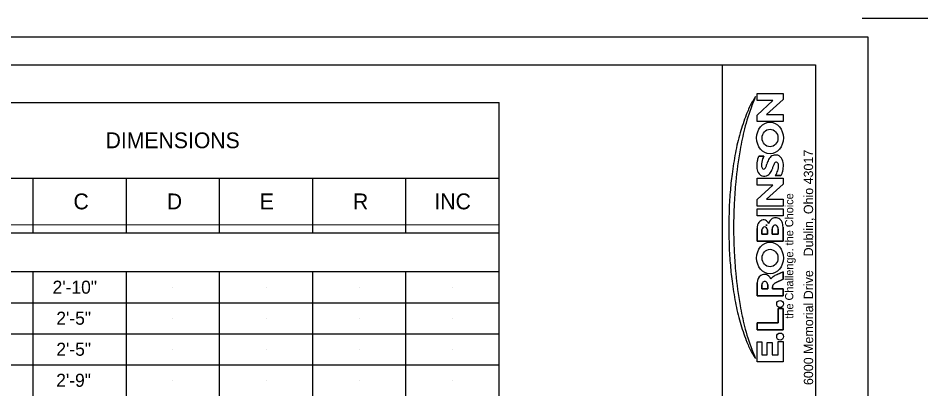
# Model space of a CAD drawing. Extents: x -9.2 to 26.7, y -0.9 to 21.1.
# Drawn here: x 16.98 to 26.74, y 17.13 to 21.11 of the extents above; entities that cross this region are included whole.
import ezdxf

# ---------------------------------------------------------------- set-up
doc = ezdxf.new("R2010")
doc.units = 0
for name, color, linetype in [('BR_P_Gen_Text', 7, 'Continuous'), ('Default', 7, 'Continuous'), ('SC_Scratch1', 7, 'Continuous'), ('SH_Border', 7, 'Continuous'), ('SH_Cut_Line', 7, 'Continuous'), ('SH_Data', 7, 'Continuous'), ('TX_P_1', 7, 'Continuous')]:
    doc.layers.add(name, color=color, linetype=linetype)

msp = doc.modelspace()

# ---------------------------------------------------------------- linework, layer by layer
at = {"layer": 'BR_P_Gen_Text'}
for p, q in [((7.6374, 20.2067), (22.1367, 20.2067)), ((22.1368, 11.7231), (22.1367, 20.2066)), ((15.1373, 19.394), (22.1368, 19.3941)), ((17.1372, 18.8063), (17.1372, 19.394)), ((18.1371, 18.8063), (18.1371, 19.394)), ((19.137, 18.8064), (19.137, 19.3941)), ((20.1369, 18.8064), (20.1369, 19.3941)), ((21.1368, 18.8064), (21.1369, 19.3941)), ((7.6374, 18.8942), (22.1367, 18.8943)), ((7.6374, 18.8066), (22.1367, 18.8066)), ((7.6374, 18.3898), (22.1367, 18.3899)), ((7.6374, 18.3898), (22.1367, 18.3899)), ((17.1372, 12.0564), (17.1372, 18.3896)), ((18.1372, 12.0564), (18.1371, 18.3896)), ((19.1371, 12.0564), (19.137, 18.3897)), ((20.137, 12.0564), (20.1369, 18.3898)), ((21.1369, 12.0564), (21.1368, 18.3898)), ((7.6374, 18.0565), (22.1367, 18.0565)), ((7.6374, 17.7232), (22.1367, 17.7232)), ((7.6374, 17.3899), (22.1367, 17.3899))]:
    msp.add_line(p, q, dxfattribs=at)
at = {"layer": 'Default'}
for p, q in [((25.163, 19.4213), (25.1012, 19.4213)), ((25.1012, 19.4213), (25.163, 19.4213)), ((24.9065, 18.7178), (24.9065, 18.8527)), ((25.1852, 18.8681), (25.1852, 18.7178)), ((24.9576, 18.8383), (24.9576, 18.7928)), ((24.9576, 18.7928), (24.9576, 18.8383)), ((25.1852, 18.7178), (24.9065, 18.7178)), ((25.1852, 18.3082), (25.1037, 18.2684)), ((25.1037, 18.2684), (25.1852, 18.3082)), ((24.9571, 18.2474), (24.9571, 18.2048)), ((24.9571, 18.2048), (24.9571, 18.2474)), ((24.9571, 18.2048), (25.0203, 18.2048)), ((25.0203, 18.2048), (24.9571, 18.2048)), ((25.0203, 18.2048), (25.0203, 18.2474)), ((25.0203, 18.2474), (25.0203, 18.2048))]:
    msp.add_line(p, q, dxfattribs=at)
for points in [[(25.1852, 20.0021), (24.9065, 20.0021), (24.9065, 20.0711), (25.075, 20.2269), (24.9065, 20.2269), (24.9065, 20.3013), (25.1852, 20.3013), (25.1852, 20.2372), (25.0077, 20.0759), (25.1852, 20.0759)], [(25.1852, 19.094), (24.9065, 19.094), (24.9065, 19.163), (25.075, 19.3189), (24.9065, 19.3189), (24.9065, 19.3933), (25.1852, 19.3933), (25.1852, 19.3291), (25.0077, 19.1679), (25.1852, 19.1679)], [(24.9065, 18.9898), (24.9065, 19.0638), (25.1852, 19.0638), (25.1852, 18.9898)], [(24.9065, 17.4223), (24.9065, 17.6368), (24.958, 17.6368), (24.958, 17.4973), (25.0152, 17.4973), (25.0152, 17.6293), (25.0667, 17.6293), (25.0667, 17.4973), (25.1337, 17.4973), (25.1337, 17.6399), (25.1852, 17.6399), (25.1852, 17.4223)]]:
    msp.add_lwpolyline(points, close=True, dxfattribs=at)
for points in [[(24.9244, 19.6286), (24.9797, 19.6286), (24.9686, 19.6018)], [(24.9686, 19.6018), (24.9797, 19.6286), (24.9244, 19.6286)], [(25.1852, 18.8681), (25.1852, 18.7178), (24.9065, 18.7178), (24.9065, 18.8527)], [(24.9065, 18.8527), (24.9065, 18.7178), (25.1852, 18.7178)], [(25.0678, 18.8473), (25.0678, 18.7928), (25.1333, 18.7928), (25.1333, 18.8473)], [(25.1333, 18.8473), (25.1333, 18.7928), (25.0678, 18.7928), (25.0678, 18.8473)], [(25.1852, 18.7178), (25.1852, 18.8681)], [(24.9576, 18.7928), (25.0167, 18.7928), (25.0167, 18.8383)], [(25.0167, 18.8383), (25.0167, 18.7928), (24.9576, 18.7928)], [(25.1204, 18.3578), (25.1852, 18.3894), (25.1852, 18.3082)], [(25.1852, 18.3082), (25.1852, 18.3894), (25.1204, 18.3578)], [(25.072, 18.2264), (25.072, 18.2048), (25.1852, 18.2048), (25.1852, 18.1298), (24.9065, 18.1298), (24.9065, 18.2048), (24.9065, 18.2691)], [(24.9065, 18.2691), (24.9065, 18.2048), (24.9065, 18.1298), (25.1852, 18.1298)], [(24.9571, 18.2474), (24.9571, 18.2048), (25.0203, 18.2048), (25.0203, 18.2474)], [(25.1852, 18.1298), (25.1852, 18.2048), (25.072, 18.2048), (25.072, 18.2264)], [(24.9065, 17.7659), (24.9065, 17.8409), (25.1337, 17.8409), (25.1337, 17.9928), (25.1852, 17.9928), (25.1852, 17.7659), (24.9065, 17.7659)], [(25.1852, 17.9928), (25.1337, 17.9928), (25.1337, 17.8409), (24.9065, 17.8409), (24.9065, 17.7659)], [(24.9065, 17.7659), (25.1852, 17.7659), (25.1852, 17.9928)]]:
    msp.add_lwpolyline(points, dxfattribs=at)
for centre, major_axis, ratio, start_param, end_param in [((25.6694, 19.5945), (0, 1.1412), 0.85, 0.988431, 1.105191), ((25.6694, 19.5945), (0, 1.1412), 0.85, 0.988431, 1.105191), ((-13.5953, 41.3688), (0, 49.9526), 0.85, 4.274094, 4.276309), ((-13.5953, 41.3688), (0, 49.9526), 0.85, 4.274094, 4.276309), ((25.1167, 20.0227), (0, 0.3626), 0.85, 0.822588, 0.988431), ((25.1167, 20.0227), (0, 0.3626), 0.85, 0.822588, 0.988431), ((26.1479, 19.454), (0, 1.6851), 0.85, 1.132502, 1.288747), ((26.1479, 19.454), (0, 1.6851), 0.85, 1.132502, 1.288747), ((27.2215, 18.8487), (0, 3.1123), 0.85, 1.165908, 1.233316), ((27.2215, 18.8487), (0, 3.1123), 0.85, 1.165908, 1.233316), ((25.2455, 19.845), (0, 0.5832), 0.85, 1.105191, 1.165908), ((25.2455, 19.845), (0, 0.5832), 0.85, 1.105191, 1.165908), ((27.6458, 18.9434), (0, 3.5199), 0.85, 1.288747, 1.354281), ((27.6458, 18.9434), (0, 3.5199), 0.85, 1.288747, 1.354281), ((26.4308, 19.1969), (0, 2.1194), 0.85, 1.243005, 1.347881), ((26.4308, 19.1969), (0, 2.1194), 0.85, 1.243005, 1.347881), ((25.0453, 19.8252), (0, -0.0938), 0.910305, 4.71238898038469, 4.712389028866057), ((27.6198, 18.9266), (0, 3.5437), 0.85, 1.360764, 1.426378), ((27.6198, 18.9266), (0, 3.5437), 0.85, 1.360764, 1.426378), ((28.8646, 18.7495), (0, 4.9633), 0.85, 1.378198, 1.448475), ((28.8646, 18.7495), (0, 4.9633), 0.85, 1.378198, 1.448475), ((24.7862, 19.6955), (0, 0.1759), 0.85, 4.250261, 4.3216), ((24.7862, 19.6955), (0, 0.1759), 0.85, 4.250261, 4.3216), ((25.1102, 19.5362), (0, 0.1096), 0.85, 0.486829, 1.030221), ((25.1102, 19.5362), (0, 0.1096), 0.85, 0.486829, 1.030221), ((25.0453, 19.8252), (0, -0.1701), 0.841969, 0, 4.84813681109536e-08), ((25.0969, 19.5658), (0, 0.0761), 0.85, 0.083326, 0.486829), ((25.0969, 19.5658), (0, 0.0761), 0.85, 0.083326, 0.486829), ((25.1024, 19.4885), (0, 0.1537), 0.85, 6.083659, 6.366511), ((25.1024, 19.4885), (0, 0.1537), 0.85, 6.083659, 6.366511), ((25.1158, 19.5665), (0, 0.0741), 0.85, 5.529173, 6.083659), ((25.1158, 19.5665), (0, 0.0741), 0.85, 5.529173, 6.083659), ((25.0638, 19.5292), (0, 0.1903), 0.85, 1.320154, 1.737094), ((25.0638, 19.5292), (0, 0.1903), 0.85, 1.320154, 1.737094), ((25.0765, 19.5254), (0, 0.2057), 0.85, 1.108668, 1.320154), ((25.0765, 19.5254), (0, 0.2057), 0.85, 1.108668, 1.320154), ((25.0486, 19.5379), (0, 0.1111), 0.85, 1.456901, 1.818883), ((25.0486, 19.5379), (0, 0.1111), 0.85, 1.456901, 1.818883), ((25.0516, 19.5375), (0, 0.1147), 0.85, 1.297264, 1.456901), ((25.0516, 19.5375), (0, 0.1147), 0.85, 1.297264, 1.456901), ((25.1183, 19.5155), (0, 0.1962), 0.85, 1.114999, 1.297264), ((25.1183, 19.5155), (0, 0.1962), 0.85, 1.114999, 1.297264), ((24.878, 19.5956), (0, 0.1654), 0.85, 4.175459, 4.396402), ((24.878, 19.5956), (0, 0.1654), 0.85, 4.175459, 4.396402), ((25.2036, 19.4703), (0, 0.2377), 0.85, 1.030221, 1.254809), ((25.2036, 19.4703), (0, 0.2377), 0.85, 1.030221, 1.254809), ((25.301, 19.4116), (0, 0.2835), 0.85, 1.063855, 1.164639), ((25.301, 19.4116), (0, 0.2835), 0.85, 1.063855, 1.164639), ((25.1129, 19.5345), (0, 0.0304), 0.85, 0.715581, 1.063855), ((25.1129, 19.5345), (0, 0.0304), 0.85, 0.715581, 1.063855), ((25.1136, 19.5335), (0, 0.0317), 0.85, 0.212074, 0.715581), ((25.1136, 19.5335), (0, 0.0317), 0.85, 0.212074, 0.715581), ((25.1126, 19.5391), (0, 0.026), 0.85, 5.247627, 6.495259), ((25.1126, 19.5391), (0, 0.026), 0.85, 5.247627, 6.495259), ((25.0505, 19.5194), (0, 0.1028), 0.85, 4.251833, 4.86616), ((25.0505, 19.5194), (0, 0.1028), 0.85, 4.251833, 4.86616), ((25.0963, 19.5277), (0, 0.0483), 0.85, 4.86616, 5.247627), ((25.0963, 19.5277), (0, 0.0483), 0.85, 4.86616, 5.247627), ((25.0957, 19.5413), (0, 0.1087), 0.85, 4.887723, 5.529173), ((25.0957, 19.5413), (0, 0.1087), 0.85, 4.887723, 5.529174), ((25.0154, 19.5246), (0, 0.2045), 0.85, 4.51081, 4.887723), ((25.0154, 19.5246), (0, 0.2045), 0.85, 4.51081, 4.887723), ((26.1994, 19.1039), (0, 1.8656), 0.85, 1.391456, 1.496401), ((26.1994, 19.1039), (0, 1.8656), 0.85, 1.391456, 1.496401), ((24.9963, 19.5159), (0, 0.1097), 0.85, 1.737094, 2.325359), ((24.9963, 19.5159), (0, 0.1097), 0.85, 1.737094, 2.325359), ((24.9756, 19.4931), (0, 0.0764), 0.85, 2.325359, 2.878408), ((24.9756, 19.4931), (0, 0.0764), 0.85, 2.325359, 2.878408), ((24.98, 19.5175), (0, 0.0279), 0.85, 1.818883, 2.384672), ((24.98, 19.5175), (0, 0.0279), 0.85, 1.818883, 2.384672), ((24.9752, 19.5115), (0, 0.0197), 0.85, 2.384672, 3.137191), ((24.9752, 19.5115), (0, 0.0197), 0.85, 2.384672, 3.137191), ((24.9752, 19.5194), (0, 0.0276), 0.85, 3.137191, 4.01614), ((24.9752, 19.5194), (0, 0.0276), 0.85, 3.137191, 4.01614), ((24.9469, 19.5473), (0, 0.071), 0.85, 4.01614, 4.175459), ((24.9469, 19.5473), (0, 0.071), 0.85, 4.01614, 4.175459), ((24.9972, 19.4926), (0, 0.0738), 0.85, 3.55749, 3.971659), ((24.9972, 19.4926), (0, 0.0738), 0.85, 3.55749, 3.971659), ((24.9527, 19.5405), (0, 0.1448), 0.85, 3.971659, 4.353371), ((24.9527, 19.5405), (0, 0.1448), 0.85, 3.971659, 4.353371), ((25.6873, 19.2162), (0, 0.7783), 0.85, 1.164639, 1.211778), ((25.6873, 19.2162), (0, 0.7783), 0.85, 1.164639, 1.211778), ((24.9236, 19.5842), (0, 0.2651), 0.85, 4.050165, 4.172563), ((24.9236, 19.5842), (0, 0.2651), 0.85, 4.050165, 4.172563), ((24.8471, 19.6382), (0, 0.37), 0.85, 4.172563, 4.251833), ((24.8471, 19.6382), (0, 0.37), 0.85, 4.172563, 4.251833), ((25.058, 19.5103), (0, 0.1522), 0.85, 4.087438, 4.318356), ((25.058, 19.5103), (0, 0.1522), 0.85, 4.087438, 4.318356), ((25.0417, 19.5183), (0, 0.173), 0.85, 4.318356, 4.51081), ((25.0417, 19.5183), (0, 0.173), 0.85, 4.318356, 4.51081), ((30.4629, 18.6831), (0, 6.8397), 0.85, 1.472392, 1.505619), ((30.4629, 18.6831), (0, 6.8397), 0.85, 1.472392, 1.505619), ((24.9838, 19.5285), (0, 0.1131), 0.85, 2.878408, 3.55749), ((24.9838, 19.5285), (0, 0.1131), 0.85, 2.878408, 3.55749), ((26.4011, 19.0027), (0, 2.1114), 0.85, 1.456986, 1.558686), ((26.4011, 19.0027), (0, 2.1114), 0.85, 1.456986, 1.558686), ((28.0071, 18.8717), (0, 3.9444), 0.85, 1.505619, 1.553601), ((28.0071, 18.8717), (0, 3.9444), 0.85, 1.505619, 1.553601), ((28.2087, 18.8097), (0, 4.2435), 0.85, 1.519271, 1.558345), ((28.2087, 18.8097), (0, 4.2435), 0.85, 1.519271, 1.558345), ((24.9758, 18.8761), (0, 0.0696), 0.85, 5.943917, 6.808987), ((24.9758, 18.8761), (0, 0.0696), 0.85, 5.943917, 6.808987), ((24.9758, 18.8761), (0, 0.0696), 0.85, 5.943917, 6.808987), ((24.9738, 18.8685), (0, 0.0776), 0.85, 5.231996, 5.947796), ((24.9738, 18.8685), (0, 0.0776), 0.85, 5.231996, 5.947796), ((24.9738, 18.8685), (0, 0.0776), 0.85, 5.231996, 5.947795), ((25.1041, 18.8782), (0, 0.0906), 0.85, 0.462144, 1.247207), ((25.1041, 18.8782), (0, 0.0906), 0.85, 0.462144, 1.247207), ((25.1041, 18.8782), (0, 0.0906), 0.85, 0.462144, 1.247207), ((25.1047, 18.8702), (0, 0.0982), 0.85, 6.14188, 6.715345), ((25.1047, 18.8702), (0, 0.0982), 0.85, 6.14188, 6.715345), ((25.1047, 18.8702), (0, 0.0982), 0.85, 6.14188, 6.715345), ((25.1088, 18.8792), (0, 0.0885), 0.85, 5.535543, 6.182102), ((25.1088, 18.8792), (0, 0.0885), 0.85, 5.535543, 6.182102), ((25.1088, 18.8792), (0, 0.0885), 0.85, 5.535543, 6.182102), ((25.114, 18.8828), (0, 0.0818), 0.85, 4.885157, 5.560215), ((25.114, 18.8828), (0, 0.0818), 0.85, 4.885157, 5.560215), ((25.114, 18.8828), (0, 0.0818), 0.85, 4.885157, 5.560215), ((28.2087, 18.9154), (0, 4.2435), 0.85, 1.583248, 1.622322), ((28.2087, 18.9154), (0, 4.2435), 0.85, 1.583248, 1.622322), ((26.5563, 18.9011), (0, 2.2373), 0.85, 1.553601, 1.587991), ((26.5563, 18.9011), (0, 2.2373), 0.85, 1.553601, 1.587991), ((26.5563, 18.8241), (0, 2.2373), 0.85, 1.553601, 1.587991), ((26.5563, 18.8241), (0, 2.2373), 0.85, 1.553601, 1.587991), ((25.0121, 18.8511), (0, 0.1243), 0.85, 1.228703, 1.558605), ((25.0121, 18.8511), (0, 0.1243), 0.85, 1.228703, 1.558605), ((25.0121, 18.8511), (0, 0.1243), 0.85, 1.228703, 1.558605), ((24.9784, 18.8622), (0, 0.0833), 0.85, 0.473795, 1.194239), ((24.9784, 18.8622), (0, 0.0833), 0.85, 0.473795, 1.194239), ((24.9784, 18.8622), (0, 0.0833), 0.85, 0.473795, 1.194239), ((24.9861, 18.8359), (0, 0.0337), 0.85, 6.249041, 7.784024), ((24.9861, 18.8359), (0, 0.0337), 0.85, 6.249041, 7.784024), ((24.9881, 18.8359), (0, 0.0337), 0.85, 4.782347, 6.317329), ((24.9881, 18.8359), (0, 0.0337), 0.85, 4.782347, 6.317329), ((25.102, 18.8496), (0, 0.0402), 0.85, 0.503186, 1.629765), ((25.102, 18.8496), (0, 0.0402), 0.85, 0.503186, 1.629765), ((25.1004, 18.8536), (0, 0.0358), 0.85, 6.277029, 6.794667), ((25.1004, 18.8536), (0, 0.0358), 0.85, 6.277029, 6.794667), ((25.1007, 18.8536), (0, 0.0358), 0.85, 5.771704, 6.289341), ((25.1007, 18.8536), (0, 0.0358), 0.85, 5.771704, 6.289341), ((25.0991, 18.8496), (0, 0.0402), 0.85, 4.65342, 5.779999), ((25.0991, 18.8496), (0, 0.0402), 0.85, 4.65342, 5.779999), ((25.0137, 18.8603), (0, 0.2019), 0.85, 4.750784, 4.89449), ((25.0137, 18.8603), (0, 0.2019), 0.85, 4.750784, 4.89449), ((25.0137, 18.8603), (0, 0.2019), 0.85, 4.750784, 4.89449), ((28.0071, 18.8535), (0, 3.9444), 0.85, 1.587991, 1.635974), ((28.0071, 18.8535), (0, 3.9444), 0.85, 1.587991, 1.635974), ((26.4011, 18.7224), (0, 2.1114), 0.85, 1.582906, 1.684607), ((26.4011, 18.7224), (0, 2.1114), 0.85, 1.582906, 1.684607), ((30.4629, 19.042), (0, 6.8397), 0.85, 1.635974, 1.669201), ((30.4629, 19.042), (0, 6.8397), 0.85, 1.635974, 1.669201), ((26.1994, 18.6213), (0, 1.8656), 0.85, 1.645192, 1.750137), ((26.1994, 18.6213), (0, 1.8656), 0.85, 1.645192, 1.750137), ((25.0453, 18.5357), (0, -0.0938), 0.910305, 4.71238898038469, 4.712389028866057), ((28.8646, 18.9757), (0, 4.9633), 0.85, 1.693118, 1.763395), ((28.8646, 18.9757), (0, 4.9633), 0.85, 1.693118, 1.763395), ((24.988, 18.2593), (0, 0.1004), 0.85, 6.102437, 6.781247), ((24.988, 18.2593), (0, 0.1004), 0.85, 6.102437, 6.781247), ((24.9869, 18.2721), (0, 0.0881), 0.85, 5.152888, 6.061538), ((24.9869, 18.2721), (0, 0.0881), 0.85, 5.152888, 6.061538), ((25.0453, 18.5357), (0, -0.1701), 0.841969, 0, 4.84813681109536e-08), ((25.2114, 18.061), (0, 0.3155), 0.85, 0.346308, 0.520291), ((25.2114, 18.061), (0, 0.3155), 0.85, 0.346308, 0.520291), ((27.6198, 18.7985), (0, 3.5437), 0.85, 1.715214, 1.780828), ((27.6198, 18.7985), (0, 3.5437), 0.85, 1.715214, 1.780828), ((24.9825, 18.2682), (0, 0.0895), 0.85, 0.482355, 1.561069), ((24.9825, 18.2682), (0, 0.0895), 0.85, 0.482355, 1.561069), ((24.9966, 18.2442), (0, 0.0467), 0.85, 1.002734, 1.50285), ((24.9966, 18.2442), (0, 0.0467), 0.85, 1.002734, 1.50285), ((24.9966, 18.2442), (0, 0.0467), 0.85, 1.002734, 1.50285), ((24.9879, 18.2473), (0, 0.0365), 0.85, 6.259044, 7.205975), ((24.9879, 18.2473), (0, 0.0365), 0.85, 6.259044, 7.205975), ((24.9879, 18.2473), (0, 0.0365), 0.85, 6.259044, 7.205975), ((24.9894, 18.2473), (0, 0.0365), 0.85, 5.360396, 6.307326), ((24.9894, 18.2473), (0, 0.0365), 0.85, 5.360396, 6.307326), ((24.9894, 18.2473), (0, 0.0365), 0.85, 5.360396, 6.307326), ((24.9807, 18.2442), (0, 0.0467), 0.85, 4.780335, 5.280452), ((24.9807, 18.2442), (0, 0.0467), 0.85, 4.780335, 5.280452), ((24.9807, 18.2442), (0, 0.0467), 0.85, 4.780335, 5.280452), ((25.1043, 18.2731), (0, 0.069), 0.85, 0.463729, 1.012038), ((25.1043, 18.2731), (0, 0.069), 0.85, 0.463729, 1.012038), ((25.1212, 18.2075), (0, 0.0643), 0.85, 0.32473, 0.965239), ((25.1212, 18.2075), (0, 0.0643), 0.85, 0.32473, 0.965239), ((25.0978, 18.2273), (0, 0.0303), 0.85, 0.984544, 1.600686), ((25.0978, 18.2273), (0, 0.0303), 0.85, 0.984544, 1.600686), ((26.4308, 18.5283), (0, 2.1194), 0.85, 1.793712, 1.898588), ((26.4308, 18.5283), (0, 2.1194), 0.85, 1.793712, 1.898588), ((27.6458, 18.7818), (0, 3.5199), 0.85, 1.787312, 1.852845), ((27.6458, 18.7818), (0, 3.5199), 0.85, 1.787312, 1.852845), ((25.1532, 18.0428), (0, -0.0377), 0.965476, 4.71238898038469, 4.712389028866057), ((27.2215, 18.8764), (0, 3.1123), 0.85, 1.908276, 1.975684), ((27.2215, 18.8764), (0, 3.1123), 0.85, 1.908276, 1.975684), ((26.1479, 18.2711), (0, 1.6851), 0.85, 1.852845, 2.009091), ((26.1479, 18.2711), (0, 1.6851), 0.85, 1.852845, 2.009091), ((25.1532, 17.693), (0, -0.0377), 0.965476, 4.71238898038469, 4.712389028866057), ((25.2455, 17.8801), (0, 0.5832), 0.85, 1.975684, 2.036401), ((25.2455, 17.8801), (0, 0.5832), 0.85, 1.975684, 2.036401), ((25.6694, 18.1307), (0, 1.1412), 0.85, 2.036401, 2.153161), ((25.6694, 18.1307), (0, 1.1412), 0.85, 2.036401, 2.153161), ((-13.5953, -3.6437), (0, 49.9526), 0.85, 5.148469, 5.150684), ((-13.5953, -3.6437), (0, 49.9526), 0.85, 5.148469, 5.150684), ((25.1167, 17.7025), (0, 0.3626), 0.85, 2.153161, 2.319004), ((25.1167, 17.7025), (0, 0.3626), 0.85, 2.153161, 2.319004)]:
    msp.add_ellipse(centre, major_axis=major_axis, ratio=ratio, start_param=start_param, end_param=end_param, dxfattribs=at)
for centre, major_axis, ratio in [((25.0453, 19.8252), (0, -0.1701), 0.841969), ((25.0453, 19.8252), (0, -0.1701), 0.841969), ((25.0453, 19.8252), (0, -0.0938), 0.910305), ((25.0453, 19.8252), (0, -0.0938), 0.910305), ((25.0453, 18.5357), (0, -0.1701), 0.841969), ((25.0453, 18.5357), (0, -0.1701), 0.841969), ((25.0453, 18.5357), (0, -0.0938), 0.910305), ((25.0453, 18.5357), (0, -0.0938), 0.910305), ((25.1532, 18.0428), (0, -0.0377), 0.965476), ((25.1532, 17.693), (0, -0.0377), 0.965476), ((25.1532, 17.693), (0, -0.0377), 0.965476)]:
    msp.add_ellipse(centre, major_axis=major_axis, ratio=ratio, dxfattribs=at)
at = {"layer": 'SC_Scratch1'}
for p, q in [((17.6371, 18.223), (17.6371, 18.223)), ((18.637, 18.223), (18.637, 18.223)), ((19.6369, 18.2231), (19.6369, 18.2231)), ((20.6369, 18.2231), (20.6369, 18.2231)), ((21.6368, 18.2231), (21.6368, 18.2231)), ((21.6368, 18.2231), (21.6368, 18.2231)), ((17.6371, 17.8897), (17.6371, 17.8897)), ((18.637, 17.8897), (18.637, 17.8897)), ((19.6369, 17.8898), (19.6369, 17.8898)), ((20.6369, 17.8898), (20.6369, 17.8898)), ((21.6368, 17.8897), (21.6368, 17.8897)), ((21.6368, 17.8897), (21.6368, 17.8897)), ((17.6371, 17.5564), (17.6371, 17.5564)), ((18.637, 17.5564), (18.637, 17.5564)), ((19.6369, 17.5564), (19.6369, 17.5564)), ((20.6369, 17.5564), (20.6369, 17.5564)), ((21.6368, 17.5564), (21.6368, 17.5564)), ((21.6368, 17.5564), (21.6368, 17.5564)), ((17.6371, 17.223), (17.6371, 17.223)), ((18.6371, 17.223), (18.6371, 17.223)), ((19.637, 17.2231), (19.637, 17.2231)), ((20.6368, 17.223), (20.6368, 17.223)), ((21.6368, 17.2231), (21.6368, 17.2231)), ((21.6368, 17.2231), (21.6368, 17.2231))]:
    msp.add_line(p, q, dxfattribs=at)
at = {"layer": 'SH_Border'}
msp.add_line((24.5337, -0.3882), (24.5337, 20.6118), dxfattribs=at)
msp.add_lwpolyline([(-5.9663, 20.6118), (25.5337, 20.6118), (25.5337, -0.3882), (-5.9663, -0.3882)], close=True, dxfattribs=at)
at = {"layer": 'SH_Cut_Line'}
msp.add_line((26.0337, 21.1118), (26.7391, 21.1118), dxfattribs=at)
msp.add_lwpolyline([(26.0962, -0.7382), (-7.9038, -0.7382), (-7.9038, 20.9118), (26.0962, 20.9118)], close=True, dxfattribs=at)

# ---------------------------------------------------------------- texts
at = {"layer": 'BR_P_Gen_Text'}
for s, p in [('2\'-10"', (17.3448, 18.153)), ('2\'-5"', (17.3846, 17.8198)), ('2\'-5"', (17.3846, 17.4865)), ('2\'-9"', (17.3835, 17.1531))]:
    msp.add_text(s, height=0.14, dxfattribs=at).set_placement(p)
at = {"layer": 'Default'}
for s, height, p in [('6000 Memorial Drive    Dublin, Ohio 43017', 0.1, (25.5081, 17.1717)), ('the Challenge. the Choice', 0.0875, (25.2951, 17.8849))]:
    msp.add_text(s, height=height, rotation=90, dxfattribs=at).set_placement(p)
at = {"layer": 'SH_Data'}
for s, p in [('.', (25.0171, 18.8654)), ("'", (25.3504, 18.8655))]:
    msp.add_text(s, height=0.125, rotation=90, dxfattribs=at).set_placement(p)
at = {"layer": 'TX_P_1'}
for s, p in [('DIMENSIONS', (17.9136, 19.7153)), ('C', (17.5689, 19.059)), ('D', (18.5708, 19.0591)), ('E', (19.568, 19.0591)), ('R', (20.5686, 19.0591)), ('INC', (21.4434, 19.0591))]:
    msp.add_text(s, height=0.17, rotation=0.00022, dxfattribs=at).set_placement(p)

doc.saveas('drawing.dxf')
